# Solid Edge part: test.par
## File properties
Author: CADCIM
Template: Normal.par
Last saved by: Cadcim
Revision: 4
Application: Solid Edge
Accuracy: 0.99
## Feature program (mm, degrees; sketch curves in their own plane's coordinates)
sketch for "unnamed Protrusion 1" #1 plane through (0, 0, 0) normal (0, 0, 1) x-axis (1, 0, 0)
  line (-47.52, 0) -> (-47.52, 46.944)
  line (-47.52, 46.944) -> (47.52, 46.944)
  line (47.52, 46.944) -> (47.52, 0)
  line (47.52, 0) -> (-47.52, 0)
sketch for "unnamed Protrusion 1" #2 plane through (0, 0, 0) normal (0, 0, 1) x-axis (1, 0, 0)
  circle centre (-33.4173, 33.1293) radius 7.1111
sketch for "unnamed Protrusion 1" #3 plane through (0, 0, 0) normal (0, 0, 1) x-axis (1, 0, 0)
  circle centre (0, 13.2015) radius 7.2161
sketch for "unnamed Protrusion 1" #4 plane through (0, 0, 0) normal (0, 0, 1) x-axis (1, 0, 0)
  circle centre (36.4831, 33.1293) radius 6.1622
extrude "unnamed Protrusion 1" add finite 6.35 along +normal
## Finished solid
Body 1: solid body, 9 faces, 18 edges, 8 vertices.
  Faces by surface: plane 6, cylinder 3
  Edges by curve: line 12, circle 6
Bounding box of the edges (mm): 95.040 x 46.944 x 6.350, from (-47.52, 0, 0) to (47.52, 46.944, 6.35).
Cylindrical faces by radius (mm): R6.1622 x1, R7.1111 x1, R7.2161 x1
Planar faces by outward normal: +x 1, +y 1, +z 1, -x 1, -y 1, -z 1
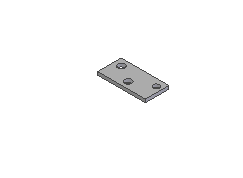
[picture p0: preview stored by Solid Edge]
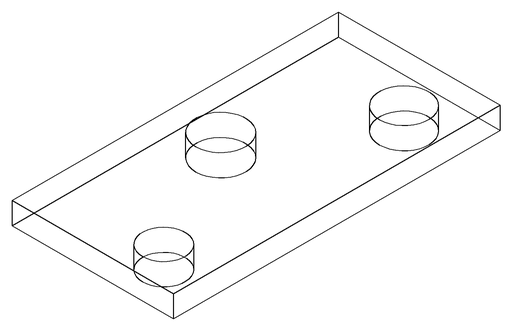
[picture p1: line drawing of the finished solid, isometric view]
